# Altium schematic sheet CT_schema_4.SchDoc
size 321 x 189 mm
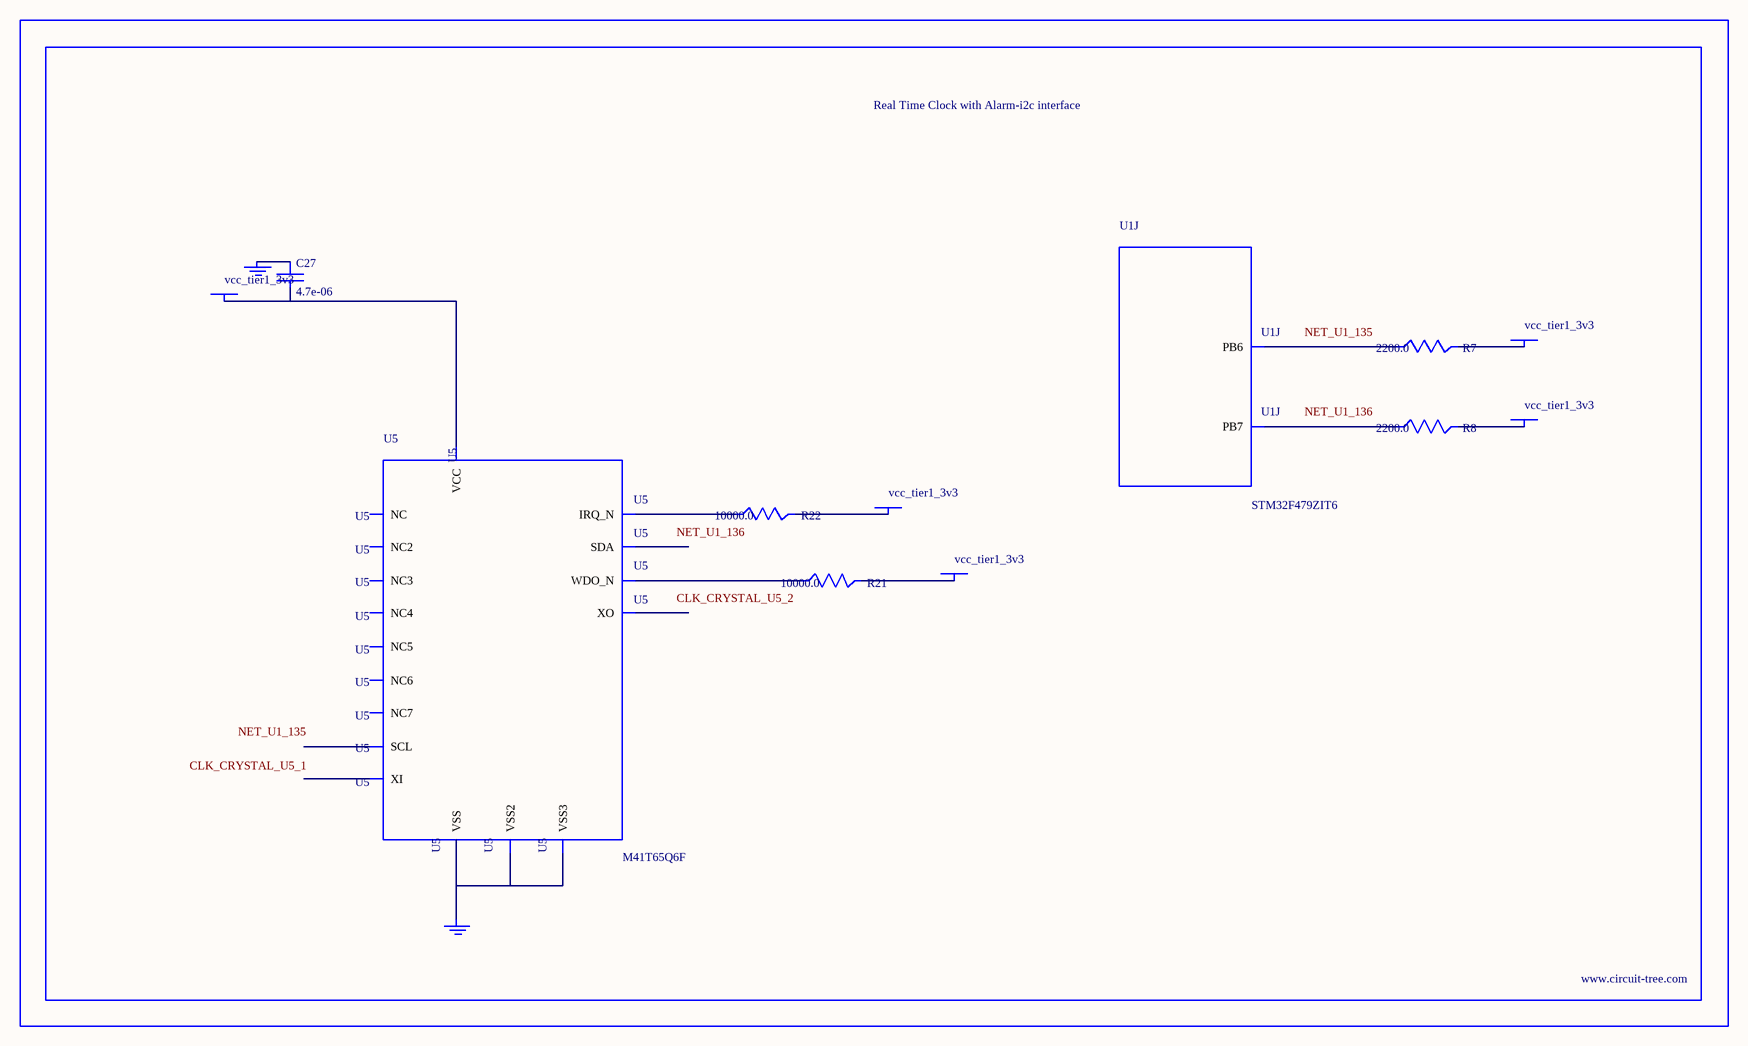
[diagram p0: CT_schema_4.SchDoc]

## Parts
BORDER3  (no value)
C27  4.7e-06  [C0805]
GND_INSTANCE_3_0  (no value)
GND_INSTANCE_3_1  (no value)
POWER_INSTANCE_3_0  vcc_tier1_3v3
POWER_INSTANCE_3_1  vcc_tier1_3v3
POWER_INSTANCE_3_2  vcc_tier1_3v3
POWER_INSTANCE_3_3  vcc_tier1_3v3
POWER_INSTANCE_3_4  vcc_tier1_3v3
R7  2200.0  [R0603]
R8  2200.0  [R0603]
R21  10000.0  [R0603]
R22  10000.0  [R0603]
U1  STM32F479ZIT6  [LQFP144]  (part J of 13)
U5  M41T65Q6F  [M41T65_QFN-16]

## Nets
NetC27_1: C27.1 GND_INSTANCE_3_0.0(GND)
NetC27_2: C27.2 POWER_INSTANCE_3_2.0(PWR) U5.14(VCC)
NetGND_INSTANCE_3_1_0: GND_INSTANCE_3_1.0(GND) U5.3(VSS) U5.5(VSS2) U5.17(VSS3)
NetPOWER_INSTANCE_3_0_0: POWER_INSTANCE_3_0.0(PWR) R21.2
NetPOWER_INSTANCE_3_1_0: POWER_INSTANCE_3_1.0(PWR) R22.2
NetPOWER_INSTANCE_3_3_0: POWER_INSTANCE_3_3.0(PWR) R7.2
NetPOWER_INSTANCE_3_4_0: POWER_INSTANCE_3_4.0(PWR) R8.2
NetR7_1: R7.1 U1.135(PB6)
NetR8_1: R8.1 U1.136(PB7)
NetR21_1: R21.1 U5.4(WDO_N)
NetR22_1: R22.1 U5.11(IRQ_N)

Not connected (* = marked no-connect by the designer): U5 1(XI) 2(XO) 6(NC) 7(NC2) 8(NC3) 9(SDA) 10(SCL) 12(NC4) 13(NC5) 15(NC6) 16(NC7)

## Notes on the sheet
- Labels drawn without touching a wire or pin: CLK_CRYSTAL_U5_1, CLK_CRYSTAL_U5_2, NET_U1_135, NET_U1_136

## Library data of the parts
BORDER3 = BORDER_PAGE3
C27 = C0805C475K4RACTU
GND_INSTANCE_3_0 GND_INSTANCE_3_1 = GND
POWER_INSTANCE_3_0-POWER_INSTANCE_3_4 = PWR
R7 R8 = RC0603JR-072K2L
R21 R22 = RC0603JR-0710KL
